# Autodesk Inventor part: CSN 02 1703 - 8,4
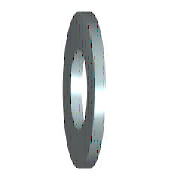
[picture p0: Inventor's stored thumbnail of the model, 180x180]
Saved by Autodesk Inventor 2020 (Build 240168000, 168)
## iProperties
Created: 2019-01
Part Number: CSN 02 1703 - 8,4
Material: Ocel, měkká
Description: Podložky pro šrouby s válcovou a půlkulovou hlavou
Document SubType Name: Modeling
Standard: CSN 02 1703
Designer: doma
Standards Organization: CSN
Language: cs-CZ
Size Designation: 8,4
Categories: <MemberInstance><Categories><Category DisplayName="Spojovací materiál" InternalName="e4da775c-781d-43d5-af7c-5136215cf5a6" Mnemonic="FSTN"><Category DisplayName
Density: 7.85 g/cm^3
Appearance: Pololeštěná
IsCustomPart: 0
Author: doma
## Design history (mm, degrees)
sketch "Náčrt"
  geometry: C1 r 7 at (0, 0); C2 r 4.2 at (0, 0); 1 further point
  constraints: 2 centre point, 2 coincident
  dimensions: "d0" = 8.4 diameter of C2 (= SD1); "d1" = 14 diameter of C1 (= SD2)
extrude "Těleso" new body sketch "Náčrt" distance "d2" = 1.6 (= SD); taper "d3" = 0 deg
workaxis "Work Axis1"
workplane "Work Plane1"
body "Solid1"
other parameters: "SD1" = 8.4 [user parameter; used in 1 equation term], "SD2" = 14 [user parameter; used in 1 equation term], "SD" = 1.6 [user parameter; used in 1 equation term], "d4" = 0, "d5" = 0, "d6" = 0, "d7" = 0, "NND" = 8 [user parameter]
